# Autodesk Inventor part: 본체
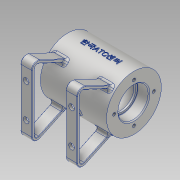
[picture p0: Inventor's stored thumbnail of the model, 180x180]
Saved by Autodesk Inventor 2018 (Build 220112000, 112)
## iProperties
Created: 2021-12
Part Number: 본체
Material: 알루미늄 6061
Document SubType Name: Modeling
Designer: home
Density: 2.7 g/cm^3
Appearance: 알루미늄 - 평지
Mass: 309.904 g
Surface Area: 352.479 cm^2
Volume: 114.779 cm^3
Author: home
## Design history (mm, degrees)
sketch "스케치1"
  geometry: L1 (-35, 0)-(35, 0); L2 (-35, 0)-(-35, 29); L3 (-35, 29)-(35, 29); L4 (35, 29)-(35, 0); L5 (-35, 16)-(-23.3, 16); L6 (-23, 15.7)-(-23, 14); L7 (-23, 14)-(-21, 14); L8 (-21, 14)-(-21, 18); L9 (-18, 21)-(18, 21); L10 (21, 18)-(21, 14); L11 (21, 14)-(23, 14); L12 (23, 14)-(23, 15.7); L13 (23.3, 16)-(35, 16); A1 r 0.3 centre (-23.3, 15.7) between (-23, 15.7) and (-23.3, 16); A2 r 0.3 centre (23.3, 15.7) between (23.3, 16) and (23, 15.7); A3 r 3 centre (-18, 18) between (-18, 21) and (-21, 18); A4 r 3 centre (18, 18) between (21, 18) and (18, 21); 6 further points
  constraints: 26 end point, 14 point on line, 8 point on circle, 8 tangent, 7 perpendicular, 4 centre point, 3 horizontal, 2 equal radius, 2 midpoint, 1 vertical
  dimensions: "d0" = 70 distance of L1.start L1.end; "d1" = 35 distance of L1.start point (0, 0); "d2" = 58 diameter of L3 L1; "d3" = 42 diameter of L9 L1; "d4" = 32 diameter of L5 L1; "d5" = 28 diameter of L7 L1; "d6" = 12 distance of L5.start point (-23, 16); "d7" = 42 distance of point (-21, 21) point (21, 21); "d8" = 12 distance of point (23, 16) L13.end; "d9" = 2 distance of L6.end L7.end; "d11" = 0.3 radius of A1; "d12" = 3 radius of A3
revolve "회전1" sketch "스케치1" stored, may be unused: angle "d10" = 90 deg
node "작업 평면1"
sketch "스케치2"
  geometry: C1 r 5 at (0, 0); 1 further point
  constraints: 1 centre point, 1 coincident
  dimensions: "d14" = 10 diameter of C1
extrude "돌출1" join sketch "스케치2" stored distance "d15" = 10; taper "d16" = 0 deg
node "작업 평면2"
sketch "스케치3"
  geometry: L1 (-55, -30.582)-(-55, 30.582); L2 (-17.993, -22.743)-(-46.464, -36.02); L3 (-46.464, 36.02)-(-17.993, 22.743); A1 r 29 centre (0, 0) between (-17.993, -22.743) and (-17.993, 22.743) reference; A2 r 6 centre (-49, -30.582) between (-55, -30.582) and (-46.464, -36.02); A3 r 6 centre (-49, 30.582) between (-46.464, 36.02) and (-55, 30.582); 3 further points
  constraints: 6 end point, 6 point on circle, 4 point on line, 4 tangent, 2 centre point, 1 equal radius, 1 vertical
  dimensions: "d18" = 80 distance of point (-55, -40) point (-55, 40); "d19" = 40 vertical distance of point (-55, -40) point (0, 0); "d20" = 65 deg angle of L1 L2; "d21" = 65 deg angle of L1 L3; "d22" = 55 distance from line of L1 point (0, 0); "d23" = 6 radius of A2
extrude "돌출2" join sketch "스케치3" distance "d24" = 12; taper "d25" = 0 deg
sketch "스케치4"
  geometry: L1 (-36.02, -46.464)-(-22.743, -17.993) reference; L2 (30.582, -55)-(-30.582, -55) reference; L3 (22.743, -17.993)-(36.02, -46.464) reference; L4 (-20.574, -20.438)-(-33.301, -47.732); L5 (-30.582, -52)-(30.582, -52); L6 (33.301, -47.732)-(20.574, -20.438); A1 r 6 centre (-30.582, -49) between (-36.02, -46.464) and (-30.582, -55) reference; A2 r 6 centre (30.582, -49) between (30.582, -55) and (36.02, -46.464) reference; A3 r 29 centre (0, 0) between (20.574, -20.438) and (-20.574, -20.438); A4 r 3 centre (-30.582, -49) between (-33.301, -47.732) and (-30.582, -52); A5 r 3 centre (30.582, -49) between (30.582, -52) and (33.301, -47.732); 1 further point
  constraints: 6 end point, 6 point on circle, 3 centre point, 1 coincident, 2 other
  dimensions: "d26" = 58 diameter of A3; "d27" = 3 distance between parallel lines of L1 L4; "d28" = 3 distance between parallel lines of L3 L6; "d29" = 3 distance between parallel lines of L2 L5
extrude "돌출3" cut sketch "스케치4" distance "d30" = 12; taper "d31" = 0 deg
sketch "스케치5" dims "d32" = 42
  geometry: 3 further points
  constraints: 2 vertical alignment, 1 coincident, 2 other
hole "구멍1" sketch "스케치5" at (0, 21) diameter "d33" = 3.242; stored, may be unused: countersink angle "d37" = 90 deg, drill point angle "d39" = 118 deg; dims "d34" = 8, "d35" = 4, "d36" = 2, "d38" = 10
sketch "스케치6"
  geometry: 2 further points
  constraints: 1 coincident
hole "구멍2" sketch "스케치6" at (0, 0) diameter "d43" = 5.188; stored, may be unused: countersink angle "d47" = 90 deg, drill point angle "d49" = 118 deg; dims "d44" = 6, "d45" = 4, "d46" = 2, "d48" = 8
sketch "스케치7"
  geometry: C1 r 2.594 at (0, 0) reference; 2 further points
  constraints: 1 coincident
hole "구멍3" sketch "스케치7" at (0, 0) diameter "d50" = 3; stored, may be unused: countersink angle "d54" = 90 deg, drill point angle "d56" = 0 deg; dims "d51" = 6, "d52" = 4, "d53" = 2, "d55" = 30
sketch "스케치8"
  geometry: L1 (6, 48.582)-(54, 48.582); L2 (54, 48.582)-(54, 12.582); L3 (54, 12.582)-(6, 12.582); L4 (6, 12.582)-(6, 48.582); L5 (6, 48.582)-(54, 12.582); L6 (54, 48.582)-(6, 12.582); C1 r 2.594 at (30, 30.582) reference; C2 r 3 at (6, 48.582); C3 r 3 at (6, 12.582); C4 r 3 at (54, 12.582); C5 r 3 at (54, 48.582); 1 further point
  constraints: 12 end point, 4 centre point, 4 coincident, 2 midpoint, 2 parallel, 1 horizontal, 1 perpendicular
  dimensions: "d57" = 48 distance of L2.end L3.end; "d58" = 36 distance of L1.end L2.end; "d59" = 6 diameter of C2; "d60" = 6 diameter of C3; "d61" = 6 diameter of C4; "d62" = 6 diameter of C5
extrude "돌출4" cut sketch "스케치8" distance "d63" = 5; taper "d64" = 0 deg
fillet "모깎기1" dims "d65" = 1
fillet "모깎기2" dims "d66" = 0.5
fillet "모깎기3" dims "d67" = 3
chamfer "모따기1" distance "d68" = 1; stored, may be unused: second distance "d69" = 2, angle "d70" = 45 deg
node "작업 평면4"
sketch "스케치9"
  geometry: L1 (-35, -29)-(-35, 29) reference; L2 (-35, 29)-(35, 29) reference; 2 further points
  constraints: 1 other
  dimensions: "d72" = 35 distance from line of L1 point (0, 0.353); "d73" = 29 distance from line of point (0, 0) L2 (derived)
feature "엠보싱1" sketch "스케치9" dims "d74" = 0.5, "d75" = 0
sketch "스케치10"
  geometry: L1 (0, 0)-(-30.07, -10.945); L2 (0, 0)-(-37, 0)
  constraints: 4 end point, 1 horizontal
  dimensions: "d76" = 20 deg angle of L2 L1; "d77" = 32 distance of L1.start L1.end
node "작업 평면5"
sketch "스케치11"
  geometry: C1 r 6 at (0, 0); 1 further point
  constraints: 1 centre point, 1 coincident
  dimensions: "d79" = 12 diameter of C1
extrude "돌출5" join sketch "스케치11" stored distance "d80" = 0; taper "d81" = 0 deg
sketch "스케치12"
  geometry: 2 further points
  constraints: 1 coincident
hole "구멍4" sketch "스케치12" at (0, 0) diameter "d82" = 5.188; stored, may be unused: countersink angle "d86" = 90 deg, drill point angle "d88" = 0 deg; dims "d83" = 30, "d84" = 4, "d85" = 2, "d87" = 30
fillet "모깎기4" dims "d89" = 1
node "솔리드1"
mirror "미러1"
pattern_circular "원형 패턴1" dims angle "d41" = 360 deg
mirror "미러2"
node "작업 평면3"
other parameters: "d13" = 32, "d71" = 29
